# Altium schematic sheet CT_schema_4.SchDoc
size 401 x 230 mm
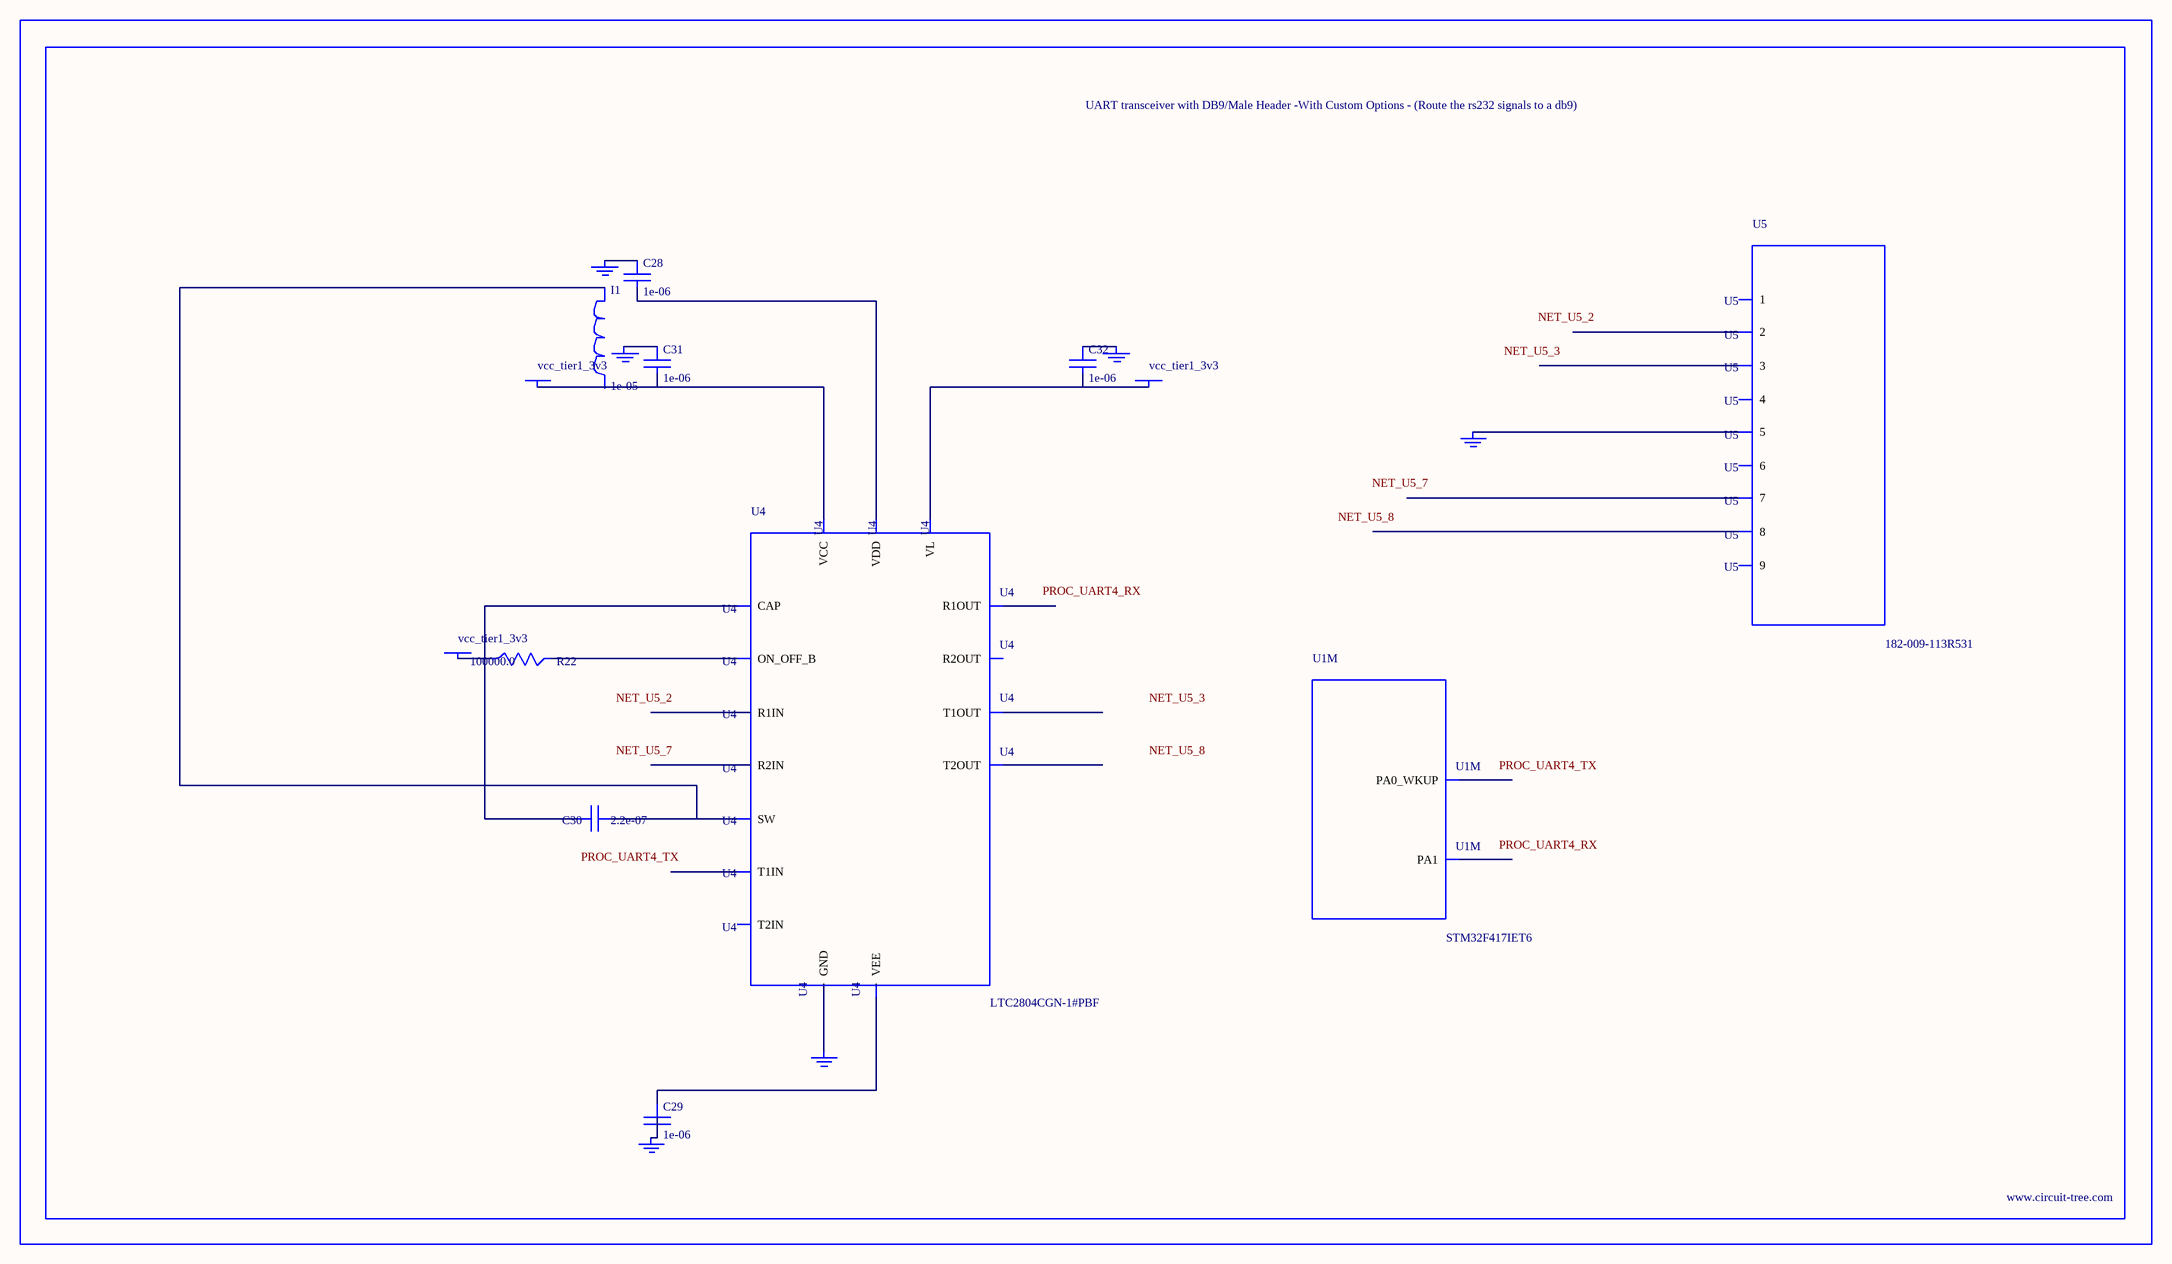
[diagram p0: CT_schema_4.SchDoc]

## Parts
BORDER3  (no value)
C28  1e-06  [C0603]
C29  1e-06  [C0603]
C30  2.2e-07  [C0603]
C31  1e-06  [C0603]
C32  1e-06  [C0603]
GND_INSTANCE_3_0  (no value)
GND_INSTANCE_3_1  (no value)
GND_INSTANCE_3_2  (no value)
GND_INSTANCE_3_3  (no value)
GND_INSTANCE_3_4  (no value)
GND_INSTANCE_3_5  (no value)
I1  1e-05  [L1210]
POWER_INSTANCE_3_0  vcc_tier1_3v3
POWER_INSTANCE_3_1  vcc_tier1_3v3
POWER_INSTANCE_3_2  vcc_tier1_3v3
R22  100000.0  [R0603]
U1  STM32F417IET6  [LQFP176]  (part M of 14)
U4  LTC2804CGN-1#PBF  [SSOP-16]
U5  182-009-113R531  [182-009-MALE]

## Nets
NetC28_1: C28.1 GND_INSTANCE_3_1.0(GND)
NetC28_2: C28.2 U4.6(VDD)
NetC29_1: C29.1 U4.9(VEE)
NetC29_2: C29.2 GND_INSTANCE_3_2.0(GND)
NetC30_1: C30.1 I1.1 U4.7(SW)
NetC30_2: C30.2 U4.10(CAP)
NetC31_1: C31.1 GND_INSTANCE_3_0.0(GND)
NetC31_2: C31.2 POWER_INSTANCE_3_0.0(PWR) U4.5(VCC)
NetC32_1: C32.1 GND_INSTANCE_3_3.0(GND)
NetC32_2: C32.2 POWER_INSTANCE_3_2.0(PWR) U4.12(VL)
NetGND_INSTANCE_3_4_0: GND_INSTANCE_3_4.0(GND) U4.8(GND)
NetGND_INSTANCE_3_5_0: GND_INSTANCE_3_5.0(GND) U5.5
NetPOWER_INSTANCE_3_1_0: POWER_INSTANCE_3_1.0(PWR) R22.1
NetR22_2: R22.2 U4.11(ON_OFF_B)

Not connected (* = marked no-connect by the designer): I1 2; U1 40(PA0_WKUP) 41(PA1); U4 1(R1IN) 2(R2IN) 3(T1OUT) 4(T2OUT) 13(T2IN) 14(T1IN) 15(R2OUT) 16(R1OUT); U5 1 2 3 4 6 7 8 9

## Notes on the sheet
- Labels drawn without touching a wire or pin: NET_U5_2, NET_U5_3, NET_U5_7, NET_U5_8, PROC_UART4_RX, PROC_UART4_TX

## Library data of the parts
BORDER3 = BORDER_PAGE3
C28 C29 C31 C32 = C0603C105K3RACTU
C30 = C0603C224K3RAC
GND_INSTANCE_3_0-GND_INSTANCE_3_5 = GND
I1 = CBC3225T100MR
POWER_INSTANCE_3_0-POWER_INSTANCE_3_2 = PWR
R22 = RC0603JR-07100KL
